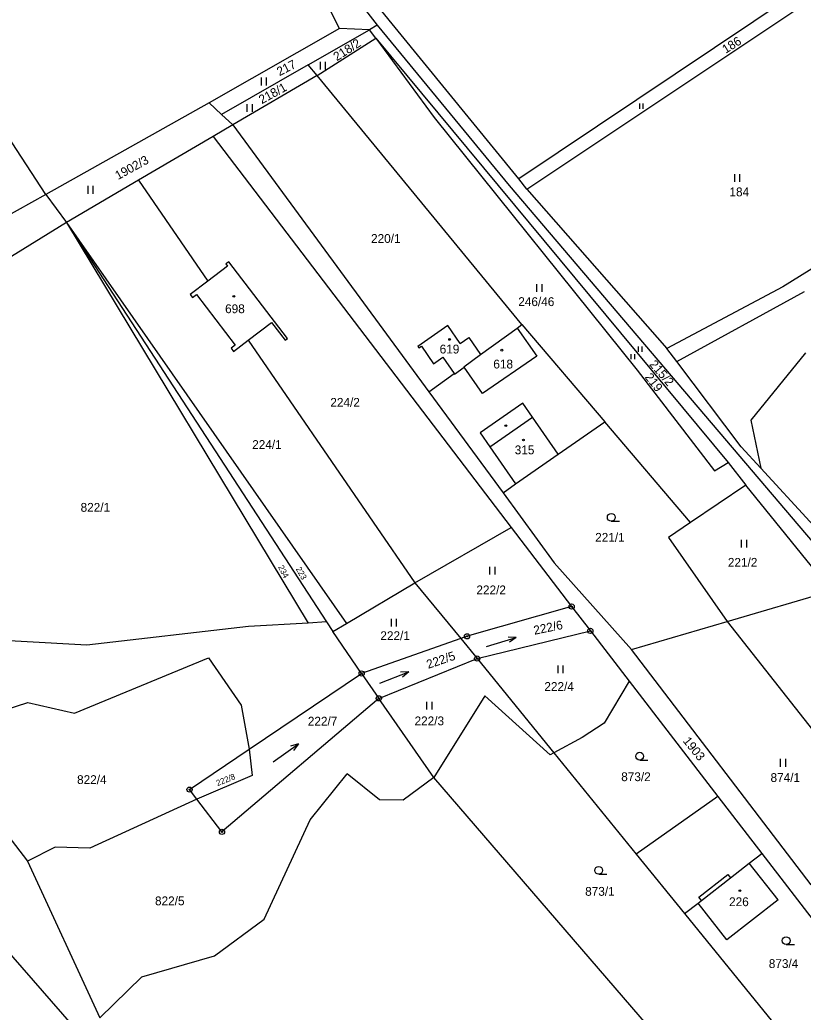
# Model space of a CAD drawing. Extents: x -445050 to -440454, y -1134563 to -1129741.
# Drawn here: x -441854.5 to -441703.6, y -1131200.4 to -1131009.2 of the extents above; entities that cross this region are included whole.
import ezdxf

# ---------------------------------------------------------------- set-up
doc = ezdxf.new("R2010")
doc.units = 0
for name, color, linetype in [('Vrstva 1', 7, 'Continuous'), ('Vrstva 18', 7, 'Continuous'), ('Vrstva 19', 7, 'Continuous'), ('Vrstva 24', 7, 'Continuous'), ('Vrstva 25', 7, 'Continuous'), ('Vrstva 3', 7, 'Continuous'), ('Vrstva 37', 7, 'Continuous'), ('Vrstva 4', 7, 'Continuous'), ('Vrstva 6', 7, 'Continuous')]:
    doc.layers.add(name, color=color, linetype=linetype)

msp = doc.modelspace()

# ---------------------------------------------------------------- linework, layer by layer
at = {"layer": 'Vrstva 1'}
for p, q in [((-441814.25, -1131055.78), (-441814.84, -1131056.22)), ((-441802.98, -1131070.58), (-441814.25, -1131055.78)), ((-441814.53, -1131056.64), (-441818.33, -1131059.52)), ((-441814.84, -1131056.22), (-441814.53, -1131056.64)), ((-441818.33, -1131059.52), (-441821.72, -1131062.09)), ((-441821.72, -1131062.09), (-441821.3, -1131062.71)), ((-441821.3, -1131062.71), (-441820.5, -1131062.1)), ((-441820.5, -1131062.1), (-441813.04, -1131071.87)), ((-441810.52, -1131070.91), (-441806.06, -1131067.49)), ((-441806.06, -1131067.49), (-441803.43, -1131070.93)), ((-441813.34, -1131073.07), (-441810.52, -1131070.91)), ((-441803.43, -1131070.93), (-441802.98, -1131070.58)), ((-441813.04, -1131071.87), (-441813.84, -1131072.46)), ((-441813.84, -1131072.46), (-441813.34, -1131073.07))]:
    msp.add_line(p, q, dxfattribs=at)
for points in [[(-441792.95, -1131010.87), (-441818.07, -1131025.2)], [(-441798.96, -1131017.83), (-441787.16, -1131011.07)], [(-441787.16, -1131011.07), (-441792.95, -1131010.87)], [(-441785.97, -1131012.72), (-441787.16, -1131011.07)], [(-441797.25, -1131019.91), (-441785.97, -1131012.72)], [(-441798.96, -1131017.83), (-441815.67, -1131027.41)], [(-441797.25, -1131019.91), (-441798.96, -1131017.83)], [(-441797.25, -1131019.91), (-441813.47, -1131029.43)], [(-441757.78, -1131067.89), (-441797.25, -1131019.91)], [(-441818.07, -1131025.2), (-441849.53, -1131042.86)], [(-441818.07, -1131025.2), (-441815.67, -1131027.41)], [(-441815.67, -1131027.41), (-441813.47, -1131029.43)], [(-441813.47, -1131029.43), (-441817.28, -1131031.66)], [(-441813.47, -1131029.43), (-441775.71, -1131080.86)], [(-441817.28, -1131031.66), (-441831.67, -1131040.1)], [(-441817.28, -1131031.66), (-441759.87, -1131106.97)], [(-441831.67, -1131040.1), (-441845.57, -1131048.25)], [(-441849.53, -1131042.86), (-441857.82, -1131047.47)], [(-441849.53, -1131042.86), (-441845.57, -1131048.25)], [(-441845.57, -1131048.25), (-441885.03, -1131072.55)], [(-441772.07, -1131068.1), (-441777.86, -1131072.12)], [(-441769.68, -1131071.54), (-441772.07, -1131068.1)], [(-441765.76, -1131073.69), (-441758.7, -1131068.56)], [(-441758.7, -1131068.56), (-441757.78, -1131067.89)], [(-441758.7, -1131068.56), (-441754.94, -1131073.96)], [(-441757.78, -1131067.89), (-441741.8, -1131086.65)], [(-441769.68, -1131071.54), (-441768.04, -1131070.4)], [(-441768.04, -1131070.4), (-441765.76, -1131073.69)], [(-441777.86, -1131072.12), (-441777.68, -1131072.39)], [(-441777.68, -1131072.39), (-441777.17, -1131072.04)], [(-441777.17, -1131072.04), (-441774.8, -1131075.44)], [(-441774.8, -1131075.44), (-441773.01, -1131074.2)], [(-441773.01, -1131074.2), (-441770.83, -1131077.34)], [(-441768.98, -1131076.01), (-441765.76, -1131073.69)], [(-441754.94, -1131073.96), (-441765.38, -1131081.21)], [(-441703.13, -1131073.35), (-441713.64, -1131086.35)], [(-441770.77, -1131077.43), (-441768.9, -1131076.13)], [(-441768.9, -1131076.13), (-441768.98, -1131076.01)], [(-441765.38, -1131081.21), (-441768.9, -1131076.13)], [(-441775.71, -1131080.86), (-441770.83, -1131077.34)], [(-441770.83, -1131077.34), (-441770.77, -1131077.43)], [(-441775.71, -1131080.86), (-441761.43, -1131100.3)], [(-441713.64, -1131086.35), (-441711.77, -1131095.59)], [(-441750.79, -1131092.9), (-441741.8, -1131086.65)], [(-441725.27, -1131106.05), (-441741.8, -1131086.65)], [(-441759, -1131098.61), (-441750.79, -1131092.9)], [(-441711.77, -1131095.59), (-441692.87, -1131116.11)], [(-441761.43, -1131100.3), (-441759, -1131098.61)], [(-441714.62, -1131098.86), (-441725.27, -1131106.05)], [(-441698.14, -1131119.18), (-441714.62, -1131098.86)], [(-441761.43, -1131100.3), (-441751.54, -1131113.78)], [(-441778.42, -1131117.65), (-441759.87, -1131106.97)], [(-441759.87, -1131106.97), (-441748.2, -1131122.24)], [(-441725.27, -1131106.05), (-441729.55, -1131108.94)], [(-441729.55, -1131108.94), (-441718.2, -1131125.13)], [(-441751.54, -1131113.78), (-441736.68, -1131130.54)], [(-441791.57, -1131125.47), (-441778.42, -1131117.65)], [(-441778.42, -1131117.65), (-441769.55, -1131128.39)], [(-441718.2, -1131125.13), (-441698.14, -1131119.18)], [(-441748.2, -1131122.24), (-441768.36, -1131127.97)], [(-441748.2, -1131122.24), (-441744.6, -1131126.92)], [(-441794.25, -1131127.06), (-441791.57, -1131125.47)], [(-441736.68, -1131130.54), (-441718.2, -1131125.13)], [(-441788.68, -1131135.12), (-441794.25, -1131127.06)], [(-441769.55, -1131128.39), (-441788.68, -1131135.12)], [(-441768.36, -1131127.97), (-441769.55, -1131128.39)], [(-441766.41, -1131132.25), (-441744.6, -1131126.92)], [(-441744.6, -1131126.92), (-441737.13, -1131136.61)], [(-441702.04, -1131175.83), (-441736.68, -1131130.54)], [(-441785.37, -1131139.93), (-441766.41, -1131132.25)], [(-441766.41, -1131132.25), (-441751.66, -1131150.4)], [(-441810.32, -1131149.72), (-441788.68, -1131135.12)], [(-441737.13, -1131136.61), (-441741.96, -1131144.73)], [(-441737.13, -1131136.61), (-441720.03, -1131158.81)], [(-441785.37, -1131139.93), (-441815.59, -1131165.65)], [(-441774.76, -1131155.19), (-441785.37, -1131139.93)], [(-441764.91, -1131139.44), (-441774.76, -1131155.19)], [(-441752.37, -1131150.78), (-441764.91, -1131139.44)], [(-441741.96, -1131144.73), (-441746.16, -1131147.44)], [(-441746.16, -1131147.44), (-441751.66, -1131150.4)], [(-441821.85, -1131157.51), (-441810.32, -1131149.72)], [(-441751.66, -1131150.4), (-441752.37, -1131150.78)], [(-441751.66, -1131150.4), (-441735.74, -1131169.97)], [(-441722.56, -1131215.75), (-441774.76, -1131155.19)], [(-441820.42, -1131159.37), (-441821.85, -1131157.51)], [(-441720.03, -1131158.81), (-441735.74, -1131169.97)], [(-441720.03, -1131158.81), (-441711.56, -1131169.81)], [(-441815.59, -1131165.65), (-441820.42, -1131159.37)], [(-441735.74, -1131169.97), (-441726.45, -1131181.4)], [(-441713.99, -1131171.71), (-441711.56, -1131169.81)], [(-441711.56, -1131169.81), (-441693.51, -1131193.26)], [(-441708.42, -1131178.75), (-441713.99, -1131171.71)], [(-441867.29, -1131176.81), (-441844.56, -1131202.79)], [(-441726.45, -1131181.4), (-441723.81, -1131179.37)], [(-441718.28, -1131186.46), (-441723.81, -1131179.37)], [(-441708.42, -1131178.75), (-441718.28, -1131186.46)], [(-441726.45, -1131181.4), (-441707.8, -1131204.33)]]:
    msp.add_lwpolyline(points, dxfattribs=at)
at = {"layer": 'Vrstva 24'}
for centre, radius in [((-441748.2, -1131122.24), 0.5), ((-441748.2, -1131122.24), 0.1), ((-441744.6, -1131126.92), 0.5), ((-441768.36, -1131127.97), 0.5), ((-441768.36, -1131127.97), 0.1), ((-441744.6, -1131126.92), 0.1), ((-441766.41, -1131132.25), 0.5), ((-441766.41, -1131132.25), 0.1), ((-441788.68, -1131135.12), 0.5), ((-441788.68, -1131135.12), 0.1), ((-441785.37, -1131139.93), 0.5), ((-441785.37, -1131139.93), 0.1), ((-441821.85, -1131157.51), 0.5), ((-441821.85, -1131157.51), 0.1), ((-441815.59, -1131165.65), 0.5), ((-441815.59, -1131165.65), 0.1)]:
    msp.add_circle(centre, radius, dxfattribs=at)
at = {"layer": 'Vrstva 25'}
for p, q in [((-441796.63, -1131018.76), (-441796.63, -1131017.26)), ((-441795.63, -1131018.76), (-441795.63, -1131017.26)), ((-441807.98, -1131021.81), (-441807.98, -1131020.31)), ((-441806.98, -1131021.81), (-441806.98, -1131020.31)), ((-441735.08, -1131026.32), (-441735.08, -1131025.31)), ((-441734.41, -1131026.32), (-441734.41, -1131025.31)), ((-441810.73, -1131026.93), (-441810.73, -1131025.43)), ((-441809.73, -1131026.93), (-441809.73, -1131025.43)), ((-441716.76, -1131040.4), (-441716.76, -1131038.9)), ((-441715.76, -1131040.4), (-441715.76, -1131038.9)), ((-441841.4, -1131042.68), (-441841.4, -1131041.18)), ((-441840.4, -1131042.68), (-441840.4, -1131041.18)), ((-441754.89, -1131061.58), (-441754.89, -1131060.08)), ((-441753.89, -1131061.58), (-441753.89, -1131060.08)), ((-441735.3, -1131073.12), (-441735.3, -1131072.11)), ((-441734.64, -1131073.12), (-441734.64, -1131072.11)), ((-441736.71, -1131074.59), (-441736.71, -1131073.58)), ((-441736.04, -1131074.59), (-441736.04, -1131073.58)), ((-441740.57, -1131105.78), (-441738.97, -1131105.78)), ((-441715.45, -1131110.88), (-441715.45, -1131109.38)), ((-441714.45, -1131110.88), (-441714.45, -1131109.38)), ((-441763.97, -1131116.08), (-441763.97, -1131114.58)), ((-441762.97, -1131116.08), (-441762.97, -1131114.58)), ((-441782.95, -1131126.08), (-441782.95, -1131124.58)), ((-441781.95, -1131126.08), (-441781.95, -1131124.58)), ((-441750.81, -1131135.07), (-441750.81, -1131133.57)), ((-441749.81, -1131135.07), (-441749.81, -1131133.57)), ((-441776.09, -1131142.1), (-441776.09, -1131140.6)), ((-441775.09, -1131142.1), (-441775.09, -1131140.6)), ((-441707.95, -1131153.1), (-441707.95, -1131151.6)), ((-441706.95, -1131153.1), (-441706.95, -1131151.6)), ((-441735.09, -1131151.82), (-441733.49, -1131151.82)), ((-441742.99, -1131173.82), (-441741.39, -1131173.82)), ((-441706.87, -1131187.36), (-441705.27, -1131187.36))]:
    msp.add_line(p, q, dxfattribs=at)
for points in [[(-441764.62, -1131129.94), (-441758.88, -1131128.2), (-441760.46, -1131128.16)], [(-441758.88, -1131128.2), (-441760.17, -1131129.12)], [(-441785.18, -1131137), (-441779.58, -1131134.84), (-441781.16, -1131134.91)], [(-441779.58, -1131134.84), (-441780.8, -1131135.85)], [(-441805.75, -1131152.15), (-441800.85, -1131148.71), (-441802.36, -1131149.16)], [(-441800.85, -1131148.71), (-441801.79, -1131149.98)]]:
    msp.add_lwpolyline(points, dxfattribs=at)
for centre, radius in [((-441813.3, -1131062.46), 0.175), ((-441771.72, -1131070.75), 0.175), ((-441761.66, -1131072.82), 0.175), ((-441760.89, -1131087.38), 0.175), ((-441757.5, -1131090.14), 0.175), ((-441740.57, -1131105.03), 0.75), ((-441735.09, -1131151.07), 0.75), ((-441742.99, -1131173.07), 0.75), ((-441715.77, -1131176.98), 0.175), ((-441706.87, -1131186.61), 0.75)]:
    msp.add_circle(centre, radius, dxfattribs=at)
at = {"layer": 'Vrstva 3'}
for points in [[(-441814.25, -1131055.78), (-441814.84, -1131056.22)], [(-441802.98, -1131070.58), (-441814.25, -1131055.78)], [(-441814.53, -1131056.64), (-441818.33, -1131059.52)], [(-441814.84, -1131056.22), (-441814.53, -1131056.64)], [(-441818.33, -1131059.52), (-441821.72, -1131062.09)], [(-441821.72, -1131062.09), (-441821.3, -1131062.71)], [(-441821.3, -1131062.71), (-441820.5, -1131062.1)], [(-441820.5, -1131062.1), (-441813.04, -1131071.87)], [(-441810.52, -1131070.91), (-441806.06, -1131067.49)], [(-441806.06, -1131067.49), (-441803.43, -1131070.93)], [(-441772.07, -1131068.1), (-441777.86, -1131072.12)], [(-441769.68, -1131071.54), (-441772.07, -1131068.1)], [(-441765.76, -1131073.69), (-441758.7, -1131068.56)], [(-441758.7, -1131068.56), (-441754.94, -1131073.96)], [(-441813.34, -1131073.07), (-441810.52, -1131070.91)], [(-441803.43, -1131070.93), (-441802.98, -1131070.58)], [(-441769.68, -1131071.54), (-441768.04, -1131070.4)], [(-441768.04, -1131070.4), (-441765.76, -1131073.69)], [(-441813.04, -1131071.87), (-441813.84, -1131072.46)], [(-441813.84, -1131072.46), (-441813.34, -1131073.07)], [(-441777.86, -1131072.12), (-441777.68, -1131072.39)], [(-441777.68, -1131072.39), (-441777.17, -1131072.04)], [(-441777.17, -1131072.04), (-441774.8, -1131075.44)], [(-441774.8, -1131075.44), (-441773.01, -1131074.2)], [(-441773.01, -1131074.2), (-441770.83, -1131077.34)], [(-441768.98, -1131076.01), (-441765.76, -1131073.69)], [(-441768.98, -1131076.01), (-441765.76, -1131073.69)], [(-441754.94, -1131073.96), (-441765.38, -1131081.21)], [(-441770.77, -1131077.43), (-441768.9, -1131076.13)], [(-441768.9, -1131076.13), (-441768.98, -1131076.01)], [(-441768.9, -1131076.13), (-441768.98, -1131076.01)], [(-441765.38, -1131081.21), (-441768.9, -1131076.13)], [(-441770.83, -1131077.34), (-441770.77, -1131077.43)], [(-441763.97, -1131091.47), (-441755.76, -1131085.76)], [(-441750.79, -1131092.9), (-441755.76, -1131085.76)], [(-441763.97, -1131091.47), (-441759, -1131098.61)], [(-441759, -1131098.61), (-441750.79, -1131092.9)], [(-441717.58, -1131174.51), (-441713.99, -1131171.71)], [(-441708.42, -1131178.75), (-441713.99, -1131171.71)], [(-441723.2, -1131178.9), (-441717.58, -1131174.51)], [(-441723.81, -1131179.37), (-441723.2, -1131178.9)], [(-441718.28, -1131186.46), (-441723.81, -1131179.37)], [(-441708.42, -1131178.75), (-441718.28, -1131186.46)]]:
    msp.add_lwpolyline(points, dxfattribs=at)
at = {"layer": 'Vrstva 37'}
for centre in [(-441813.3, -1131062.46), (-441771.72, -1131070.75), (-441761.66, -1131072.82), (-441757.5, -1131090.14), (-441715.77, -1131176.98)]:
    msp.add_circle(centre, 0.175, dxfattribs=at)
at = {"layer": 'Vrstva 4'}
for points in [[(-441757.64, -1131083.05), (-441765.85, -1131088.76)], [(-441755.76, -1131085.76), (-441757.64, -1131083.05)], [(-441763.97, -1131091.47), (-441755.76, -1131085.76)], [(-441750.79, -1131092.9), (-441755.76, -1131085.76)], [(-441765.85, -1131088.76), (-441763.97, -1131091.47)], [(-441763.97, -1131091.47), (-441759, -1131098.61)], [(-441717.58, -1131174.51), (-441713.99, -1131171.71)], [(-441723.72, -1131178.23), (-441718.08, -1131173.86)], [(-441723.2, -1131178.9), (-441717.58, -1131174.51)], [(-441718.08, -1131173.86), (-441717.58, -1131174.51)], [(-441723.2, -1131178.9), (-441723.72, -1131178.23)], [(-441723.81, -1131179.37), (-441723.2, -1131178.9)]]:
    msp.add_lwpolyline(points, dxfattribs=at)
at = {"layer": 'Vrstva 6'}
for p, q in [((-441831.67, -1131040.1), (-441818.33, -1131059.52)), ((-441810.52, -1131070.91), (-441778.42, -1131117.65))]:
    msp.add_line(p, q, dxfattribs=at)
for points in [[(-441849.53, -1131042.86), (-441907.31, -1130954.23)], [(-441822.39, -1130962.93), (-441785.69, -1131010.21)], [(-441792.95, -1131010.87), (-441802.67, -1130991.5)], [(-441758.41, -1131039.83), (-441795.13, -1130994.8)], [(-441705.49, -1131004.38), (-441758.41, -1131039.83)], [(-441756.82, -1131041.79), (-441703.87, -1131006.48)], [(-441785.69, -1131010.21), (-441787.16, -1131011.07)], [(-441785.69, -1131010.21), (-441760.22, -1131041.12)], [(-441785.97, -1131012.72), (-441718.05, -1131094.49)], [(-441785.97, -1131012.72), (-441774.67, -1131028.01)], [(-441774.67, -1131028.01), (-441735.59, -1131076.71)], [(-441756.82, -1131041.79), (-441758.41, -1131039.83)], [(-441672.63, -1131039.01), (-441707.52, -1131060.64)], [(-441760.22, -1131041.12), (-441695.25, -1131117.45)], [(-441756.82, -1131041.79), (-441729.84, -1131072.5)], [(-441845.57, -1131048.25), (-441791.57, -1131125.47)], [(-441845.57, -1131048.25), (-441795.46, -1131125.21)], [(-441845.57, -1131048.25), (-441799.01, -1131125.42)], [(-441707.52, -1131060.64), (-441729.84, -1131072.5)], [(-441727.93, -1131075.04), (-441703.3, -1131061.51)], [(-441727.93, -1131075.04), (-441729.84, -1131072.5)], [(-441715.55, -1131091.48), (-441727.93, -1131075.04)], [(-441735.59, -1131076.71), (-441720.68, -1131096.06)], [(-441715.55, -1131091.48), (-441711.77, -1131095.59)], [(-441720.68, -1131096.06), (-441718.05, -1131094.49)], [(-441718.05, -1131094.49), (-441714.62, -1131098.86)], [(-441810.48, -1131126.1), (-441841.62, -1131129.69)], [(-441799.01, -1131125.42), (-441810.48, -1131126.1)], [(-441795.46, -1131125.21), (-441799.01, -1131125.42)], [(-441795.46, -1131125.21), (-441794.25, -1131127.06)], [(-441718.2, -1131125.13), (-441678.93, -1131175.01)], [(-441841.62, -1131129.69), (-441878.51, -1131127.6)], [(-441769.55, -1131128.39), (-441766.41, -1131132.25)], [(-441844.04, -1131142.79), (-441818.2, -1131132.13)], [(-441818.2, -1131132.13), (-441811.9, -1131141.23)], [(-441788.68, -1131135.12), (-441785.37, -1131139.93)], [(-441871.92, -1131146.83), (-441852.99, -1131140.71)], [(-441852.99, -1131140.71), (-441844.04, -1131142.79)], [(-441811.9, -1131141.23), (-441810.32, -1131149.72)], [(-441871.92, -1131146.83), (-441853.04, -1131171.29)], [(-441810.32, -1131149.72), (-441809.77, -1131154.81)], [(-441809.77, -1131154.81), (-441820.42, -1131159.37)], [(-441798.58, -1131163.36), (-441791.47, -1131154.45)], [(-441785.25, -1131159.49), (-441791.47, -1131154.45)], [(-441774.76, -1131155.19), (-441780.65, -1131159.55)], [(-441820.42, -1131159.37), (-441841.03, -1131168.78)], [(-441780.65, -1131159.55), (-441785.25, -1131159.49)], [(-441807.45, -1131182.45), (-441798.58, -1131163.36)], [(-441847.75, -1131168.57), (-441853.04, -1131171.29)], [(-441841.03, -1131168.78), (-441847.75, -1131168.57)], [(-441853.04, -1131171.29), (-441839.15, -1131201.5)], [(-441817.03, -1131189.53), (-441807.45, -1131182.45)], [(-441831.04, -1131193.6), (-441817.03, -1131189.53)], [(-441839.15, -1131201.5), (-441831.04, -1131193.6)]]:
    msp.add_lwpolyline(points, dxfattribs=at)

# ---------------------------------------------------------------- texts
at = {"layer": 'Vrstva 18'}
for s, height, rotation, p in [('218/2', 1.7, 32.5071, (-441793.46, -1131017.18)), ('186', 1.7, 32.0058, (-441718.53, -1131015.74)), ('217', 1.7, 27.2583, (-441804.5, -1131020.05)), ('218/1', 1.7, 28.7568, (-441807.91, -1131025.44)), ('1902/3', 1.7, 28.8801, (-441835.62, -1131040.06)), ('215/2', 1.7, 310.8024, (-441733.34, -1131075.63)), ('219', 1.7, 308.3976, (-441734.2, -1131078.06)), ('234', 1.14, 297.3082, (-441804.81, -1131114.62)), ('223', 1.14, 299.4454, (-441801.41, -1131114.98)), ('222/6', 1.7, 11.6604, (-441755.36, -1131127.68)), ('222/5', 1.7, 18.7911, (-441775.84, -1131134.25)), ('1903', 1.7, 308.9214, (-441726.85, -1131148.18)), ('222/8', 1.14, 21.946, (-441816.44, -1131156.85))]:
    msp.add_text(s, height=height, rotation=rotation, dxfattribs=at).set_placement(p)
for s, p in [('184', (-441717.79, -1131043.18)), ('220/1', (-441786.86, -1131052.16)), ('246/46', (-441758.49, -1131064.33)), ('224/2', (-441794.71, -1131083.74)), ('224/1', (-441809.77, -1131091.87)), ('822/1', (-441842.84, -1131103.97)), ('221/1', (-441743.67, -1131109.75)), ('221/2', (-441718.1, -1131114.57)), ('222/2', (-441766.56, -1131119.88)), ('222/1', (-441785.07, -1131128.7)), ('222/4', (-441753.46, -1131138.49)), ('222/7', (-441799.05, -1131145.18)), ('222/3', (-441778.48, -1131145.12)), ('822/4', (-441843.52, -1131156.44)), ('873/2', (-441738.65, -1131155.88)), ('874/1', (-441709.87, -1131156.04)), ('873/1', (-441745.6, -1131177.97)), ('822/5', (-441828.5, -1131179.8)), ('873/4', (-441710.21, -1131191.89))]:
    msp.add_text(s, height=1.7, dxfattribs=at).set_placement(p)
at = {"layer": 'Vrstva 19'}
for s, p in [('698', (-441814.99, -1131065.7)), ('619', (-441773.64, -1131073.47)), ('618', (-441763.3, -1131076.36)), ('315', (-441759.17, -1131092.9)), ('226', (-441717.86, -1131179.97))]:
    msp.add_text(s, height=1.7, dxfattribs=at).set_placement(p)

doc.saveas('drawing.dxf')
